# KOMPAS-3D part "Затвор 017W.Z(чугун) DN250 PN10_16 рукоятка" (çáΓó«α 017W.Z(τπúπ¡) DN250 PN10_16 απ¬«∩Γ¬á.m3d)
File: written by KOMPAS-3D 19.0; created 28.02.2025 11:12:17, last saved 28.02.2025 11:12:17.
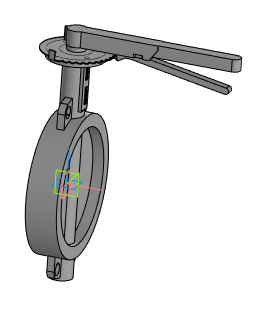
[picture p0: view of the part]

Document properties: Автор: Евгений; Полное имя файла: Затвор 017W.Z(чугун) DN250 PN10_16 рукоятка.a3d

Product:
- Part/product: Затвор 017W.Z(чугун) DN250 PN10_16 рукоятка
    Масса: 31.3674

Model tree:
1. Операция без истории:1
